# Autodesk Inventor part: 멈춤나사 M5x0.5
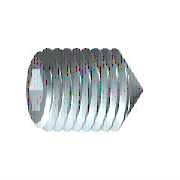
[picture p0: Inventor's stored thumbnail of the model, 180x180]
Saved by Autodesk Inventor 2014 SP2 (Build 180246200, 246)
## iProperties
Company: 한국ATC센터
IsCustomPart: 1
Created: 2014-11
Part Number: 멈춤나사 M5x0.5
Material: 강, 연강
Description: 6각 소켓 머리 없는 멈춤 나사
Document SubType Name: Modeling
Standard: KS B 1028
Designer: KYOUNG IL JANG
Standards Organization: KS
Language: ko-KR
Size Designation: 원추점 M5x10
Categories: <MemberInstance><Categories><Category DisplayName="조임쇠" InternalName="e4da775c-781d-43d5-af7c-5136215cf5a6" Mnemonic="FSTN"><Category DisplayName="볼트" InternalN
Density: 7.86 g/cm^3
Mass: 1.16912 g
Surface Area: 1.91683 cm^2
Volume: 0.148743 cm^3
Appearance: 강철
Author: KYOUNG IL JANG
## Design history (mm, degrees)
sketch "스케치1"
  geometry: L1 (0, 0)-(6.167, 0); L2 (10, 1.443)-(10, 2.5); L3 (10, 2.5)-(0, 2.5); L4 (10, 1.443)-(7, 1.443); L5 (7, 1.443)-(6.167, 0); L6 (0, -0.5)-(0, 3) reference; L7 (0, 2.5)-(0, 0)
  constraints: 13 end point, 3 parallel, 1 collinear, 1 perpendicular, 1 point on line
  dimensions: "d0" = 3 distance of L2.start L4.end (= INTI); "d1" = 60 deg angle of L5 L1; "d2" = 5 diameter of L3 L1 (= NND); "d3" = 2.88675 diameter of L4 L1 (= 1.1547 x SW); "d5" = 10 distance from line of L2 L3.end (= NLG)
revolve "본체" sketch "스케치1" stored, may be unused: angle "d6" = 90 deg
sketch "스케치2"
  geometry: L1 (-0.722, 1.25)-(0.722, 1.25); L2 (0.722, 1.25)-(1.443, 0); L3 (1.443, 0)-(0.722, -1.25); L4 (0.722, -1.25)-(-0.722, -1.25); L5 (-0.722, -1.25)-(-1.443, 0); L6 (-1.443, 0)-(-0.722, 1.25); 3 further points
  constraints: 12 end point, 1 coincident, 1 horizontal, 13 other
extrude "슬롯" join sketch "스케치2" taper "d7" = 0 deg; stored distance "d21" = 10
workaxis "Work Axis1"
workplane "Work Plane1"
body "Solid1"
feature "스레드" dims "d12" = 10 (= NLG), "d13" = 0
chamfer "모따기1" distance "d8" = 2.25 (computed from NND, SPD, FAWI); stored, may be unused: angle "d9" = 45 deg (= FAWI), second distance "d34" = 2.25 (computed from NND, SPD, FAWI)
chamfer "모따기2" distance "d10" = 0.49076 (= -0.5 x GD1 + 0.5 x NND); stored, may be unused: angle "d11" = 45 deg (= FAWI), second distance "d35" = 0.49076 (= -0.5 x GD1 + 0.5 x NND)
other parameters: "NND" = 5 [user parameter; used in 5 equation terms], "NLG" = 10 [user parameter; used in 2 equation terms], "INTI" = 3 [user parameter; used in 1 equation term], "FAWI" = 45 deg [user parameter; used in 4 equation terms], "SW" = 2.5 [user parameter; used in 2 equation terms], "GD1" = 4.01848 (= THREADDIA - 1.2269 x PTC) [user parameter; used in 2 equation terms], "d4" = 0, "FAWI1" = 45 deg [user parameter], "SPD" = 0.5 [user parameter; used in 2 equation terms], "d36" = 0, "d37" = 0, "GUL" = 0.49076 (= 0.61345 x PTC) [user parameter], "TPU" = 12.5 (computed from PTC) [user parameter], "TOA" = 30 deg [user parameter], "THREADDIA" = 5 [user parameter; used in 1 equation term], "PTC" = 0.8 [user parameter; used in 4 equation terms], "GAL" = 0.49076 (= 0.61345 x PTC) [user parameter], "E0" = 2.8875 (= 1.155 x SW) [user parameter]
